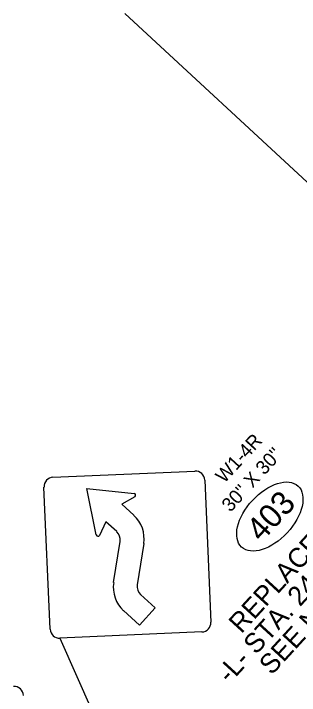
# Model space of a CAD drawing. Extents: x 1768295 to 1769615, y 998972 to 1001024.
# Drawn here: x 1768947.4 to 1769123.6, y 1000604.8 to 1001024.3 of the extents above; entities that cross this region are included whole.
import ezdxf

# ---------------------------------------------------------------- set-up
doc = ezdxf.new("R2010")
doc.units = 0
for name, color, linetype in [('O_GS_Sht', 7, 'Continuous'), ('P_NCDOT_Horizontal_Alignment_Tick_Large', 7, 'Continuous'), ('SheetLines_dp', 7, 'Continuous'), ('TextMinor', 7, 'Continuous')]:
    doc.layers.add(name, color=color, linetype=linetype)

msp = doc.modelspace()

# ---------------------------------------------------------------- linework, layer by layer
at = {"layer": 'O_GS_Sht'}
for p, q in [((1769065.2, 1000737.27), (1769069.01, 1000649.8)), ((1768992.6, 1000732.16), (1769021.68, 1000728.99)), ((1768998.37, 1000703.55), (1768992.6, 1000732.16)), ((1769022.16, 1000726.95), (1769014.16, 1000722.33)), ((1769014.16, 1000722.33), (1769021.52, 1000715.58)), ((1769004.35, 1000711.62), (1769000.43, 1000703.24)), ((1769011.03, 1000705.5), (1769004.35, 1000711.62)), ((1769009.1, 1000674.18), (1769013.1, 1000699.51)), ((1769027.63, 1000698.17), (1769023.55, 1000672.75)), ((1769025.7, 1000666.84), (1769034.69, 1000658.6)), ((1769034.69, 1000658.6), (1769024.96, 1000647.98)), ((1769024.96, 1000647.98), (1769015.2, 1000656.93))]:
    msp.add_line(p, q, dxfattribs=at)
for points in [[(1768971.7, 1000738.99), (1769059.17, 1000742.8)], [(1768969.99, 1000645.48), (1768966.17, 1000732.96)], [(1769063.49, 1000643.77), (1768976.01, 1000639.96)]]:
    msp.add_lwpolyline(points, dxfattribs=at)
for centre, radius, start, end in [((1769059.43, 1000737.02), 5.78, 2.4947, 92.4947), ((1768971.95, 1000733.21), 5.78, 92.4816, 137.4882), ((1768971.95, 1000733.21), 5.78, 137.4882, 182.4947), ((1769021.53, 1000727.85), 1.1, 304.925, 83.5869), ((1769008.44, 1000701.22), 19.42, 351.072, 47.4947), ((1769006.53, 1000700.59), 6.64, 351.0721, 47.4947), ((1768999.47, 1000703.78), 1.1, 191.4025, 330.0643), ((1769028.29, 1000671.19), 19.42, 171.072, 227.4947), ((1769030.19, 1000671.73), 6.64, 171.0719, 227.4947), ((1769063.24, 1000649.55), 5.78, 317.4947, 2.4947), ((1768975.76, 1000645.74), 5.78, 182.4947, 272.4947), ((1769063.24, 1000649.55), 5.78, 272.4947, 317.4947)]:
    msp.add_arc(centre, radius, start, end, dxfattribs=at)
at = {"layer": 'P_NCDOT_Horizontal_Alignment_Tick_Large'}
msp.add_line((1769248.21, 1000809.69), (1769016.02, 1001024.3), dxfattribs=at)
at = {"layer": 'SheetLines_dp'}
msp.add_arc((1768947.7, 1000604.5), 5.78, 2.4947, 92.4947, dxfattribs=at)
at = {"layer": 'TextMinor'}
msp.add_line((1768976.01, 1000639.96), (1769076.78, 1000411.53), dxfattribs=at)
msp.add_ellipse((1769105.34, 1000714.8), major_axis=(-17.4, -18.8), ratio=0.571429, dxfattribs=at)

# ---------------------------------------------------------------- texts
at = {"layer": 'O_GS_Sht'}
for s, height, p in [('W1-4R', 8.515, (1769077.29, 1000734.85)), ("30'' X 30''", 8.5154, (1769081.09, 1000717.09))]:
    msp.add_text(s, height=height, rotation=47.4947, dxfattribs=at).set_placement(p)
at = {"layer": 'TextMinor'}
for s, height, rotation, p in [('403', 14.463, 47.2172, (1769100.14, 1000698.54)), ('-L- STA. 24+07+/-', 12, 47.4947, (1769080.55, 1000611.59)), ('REPLACE', 12, 47.4947, (1769087.77, 1000642.29)), ('SEE NOTE 3', 12, 47.4947, (1769106.46, 1000616.75))]:
    msp.add_text(s, height=height, rotation=rotation, dxfattribs=at).set_placement(p)

doc.saveas('drawing.dxf')
